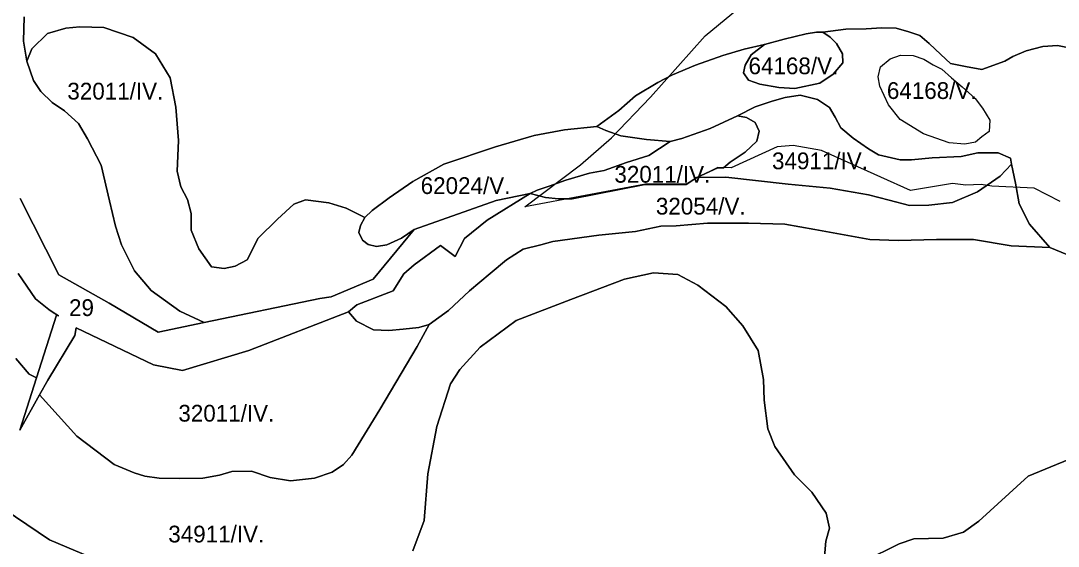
# Model space of a CAD drawing. Extents: x -521621 to -516761, y -1190184 to -1184927.
# Drawn here: x -518666 to -517738, y -1186473 to -1186003 of the extents above; entities that cross this region are included whole.
import ezdxf

# ---------------------------------------------------------------- set-up
doc = ezdxf.new("R2010")
doc.units = 0
doc.layers.add('BPEJ_s', color=7, linetype='Continuous')
doc.layers.add('odvodneni_s', color=7, linetype='Continuous')

msp = doc.modelspace()

# ---------------------------------------------------------------- linework, layer by layer
at = {"layer": 'BPEJ_s'}
for points in [[(-518663.33, -1185999.19), (-518663.92, -1186020.8), (-518660.96, -1186038.86), (-518655.06, -1186055.93), (-518648.33, -1186066.04), (-518638.23, -1186075.72), (-518627.28, -1186083.3), (-518614.66, -1186094.67), (-518606.66, -1186108.15), (-518594.46, -1186131.73), (-518586.88, -1186163.74), (-518581.41, -1186186.48), (-518576.05, -1186203.16), (-518564.51, -1186226.26), (-518549.71, -1186244.02), (-518523.97, -1186262.37), (-518502.28, -1186272.68), (-518543.48, -1186281.2), (-518587.23, -1186255.36), (-518632.34, -1186230.07), (-518666.87, -1186161.64)], [(-517723.47, -1186027.82), (-517738.12, -1186024.66), (-517751.18, -1186025.57), (-517766.28, -1186029.4), (-517778.07, -1186034.66), (-517785.38, -1186038.88), (-517805.91, -1186046.19), (-517820.53, -1186043.66), (-517834.02, -1186040.84), (-517842.74, -1186032.69), (-517853.14, -1186022.84), (-517861.3, -1186015.81), (-517871.42, -1186012.43), (-517882.67, -1186009.34), (-517895.32, -1186009.05), (-517909.38, -1186009.9), (-517927.65, -1186010.18), (-517948.18, -1186012.71), (-517954.08, -1186012.71), (-517963.08, -1186014.4), (-517982.76, -1186019.18), (-518000.47, -1186023.97), (-518018.75, -1186027.9), (-518037.87, -1186033.81), (-518062.33, -1186042.25), (-518082.86, -1186050.97), (-518096.07, -1186057.73), (-518116.03, -1186069.82), (-518130.93, -1186083.05), (-518150.62, -1186097.11), (-518179.58, -1186100.21), (-518206.57, -1186105.27), (-518241.43, -1186115.4), (-518287.54, -1186130.87), (-518315.38, -1186146.34), (-518336.47, -1186160.97), (-518351.65, -1186172.51), (-518358.4, -1186178.7), (-518374.99, -1186170.26), (-518390.45, -1186165.48), (-518411.54, -1186162.94), (-518421.91, -1186166.68), (-518436.64, -1186180.16), (-518453.89, -1186197), (-518463.57, -1186216.37), (-518474.51, -1186222.27), (-518484.19, -1186224.37), (-518495.56, -1186222.69), (-518506.92, -1186206.69), (-518513.65, -1186189.84), (-518513.65, -1186175.1), (-518517.02, -1186162.47), (-518522.91, -1186151.1), (-518526.28, -1186137.21), (-518525.02, -1186109.83), (-518527.54, -1186079.93), (-518532.59, -1186053.82), (-518545.64, -1186032.35), (-518565.84, -1186017.61), (-518591.93, -1186008.77), (-518613.33, -1186008.07), (-518626.05, -1186009.25), (-518642.32, -1186013.99), (-518656.52, -1186027.61), (-518660.96, -1186038.86), (-518663.92, -1186020.8), (-518663.33, -1185999.19)], [(-517724.74, -1186213.79), (-517745.18, -1186205.51), (-517763.2, -1186184.56), (-517772.44, -1186166.54), (-517775.85, -1186148.03), (-517779.26, -1186130.98), (-517780.23, -1186125.62), (-517791.43, -1186120.75), (-517809.44, -1186120.75), (-517824.54, -1186124.16), (-517850.34, -1186125.14), (-517868.84, -1186127.08), (-517879.06, -1186127.08), (-517898.53, -1186122.7), (-517907.3, -1186117.34), (-517921.18, -1186107.8), (-517932.15, -1186098.52), (-517937.21, -1186088.95), (-517942.27, -1186080.23), (-517952.96, -1186073.2), (-517968.42, -1186069.26), (-517981.92, -1186071.23), (-517993.73, -1186074.6), (-518008.91, -1186079.67), (-518024.65, -1186087.83), (-518049.12, -1186099.08), (-518074.42, -1186108.08), (-518084.82, -1186110.62), (-518106.19, -1186108.93), (-518129.25, -1186105.55), (-518142.46, -1186100.77), (-518150.62, -1186097.11), (-518130.93, -1186083.05), (-518116.03, -1186069.82), (-518096.07, -1186057.73), (-518082.86, -1186050.97), (-518062.33, -1186042.25), (-518037.87, -1186033.81), (-518018.75, -1186027.9), (-518000.47, -1186023.97), (-518012.56, -1186033.25), (-518017.91, -1186042.25), (-518019.31, -1186049.29), (-518014.81, -1186055.76), (-518004.69, -1186059.41), (-517987.54, -1186062.23), (-517973.48, -1186063.35), (-517950.99, -1186058.57), (-517938.9, -1186050.41), (-517930.46, -1186040.28), (-517930.75, -1186032.12), (-517936.09, -1186022.84), (-517941.71, -1186017.21), (-517948.18, -1186012.71), (-517927.65, -1186010.18), (-517909.38, -1186009.9), (-517895.32, -1186009.05), (-517882.67, -1186009.34), (-517871.42, -1186012.43), (-517861.3, -1186015.81), (-517853.14, -1186022.84), (-517842.74, -1186032.69), (-517834.02, -1186040.84), (-517820.53, -1186043.66), (-517805.91, -1186046.19), (-517785.38, -1186038.88), (-517778.07, -1186034.66), (-517766.28, -1186029.4), (-517751.18, -1186025.57), (-517738.12, -1186024.66), (-517723.47, -1186027.82)], [(-518666.87, -1186161.64), (-518632.34, -1186230.07), (-518587.23, -1186255.36), (-518543.48, -1186281.2), (-518502.28, -1186272.68), (-518398.58, -1186251.24), (-518388.54, -1186249.6), (-518350.76, -1186233.82), (-518314.06, -1186189.3), (-518240.84, -1186163.54), (-518210.39, -1186157.15), (-518248.83, -1186181.17), (-518269.07, -1186197.45), (-518277.37, -1186213.57), (-518290.59, -1186203.73), (-518314, -1186220.9), (-518323.49, -1186229.17), (-518332.99, -1186244.14), (-518365.52, -1186256.64), (-518373.06, -1186263.06), (-518462.29, -1186297.62), (-518521.64, -1186315.37), (-518547.55, -1186310.37), (-518616.73, -1186277.29), (-518618.04, -1186284.1), (-518642.2, -1186324.24), (-518649.43, -1186337.23), (-518667.13, -1186369), (-518652.28, -1186322.17), (-518634.49, -1186266.09), (-518632.69, -1186266.61), (-518638.34, -1186263), (-518641.17, -1186260.95), (-518653.25, -1186251.43), (-518668.53, -1186228.68)], [(-518670.73, -1186304.88), (-518658.79, -1186318.79), (-518652.28, -1186322.17), (-518667.13, -1186369), (-518649.43, -1186337.23), (-518616.27, -1186374.14), (-518582.58, -1186399.67), (-518564.92, -1186407.2), (-518555.21, -1186409.96), (-518542.56, -1186411.92), (-518524.29, -1186412.21), (-518503.2, -1186411.92), (-518488.3, -1186409.11), (-518477.33, -1186405.74), (-518459.9, -1186405.45), (-518443.03, -1186411.36), (-518424.75, -1186414.18), (-518403.38, -1186411.93), (-518387.64, -1186406.58), (-518377.52, -1186399.55), (-518369.85, -1186391.33), (-518344.96, -1186350.52), (-518311.57, -1186294), (-518300.57, -1186274.34), (-518283.33, -1186261.69), (-518264.49, -1186244.25), (-518246.21, -1186228.78), (-518231.59, -1186216.4), (-518216.69, -1186207.11), (-518200.66, -1186203.17), (-518189.98, -1186200.08), (-518148.78, -1186194.48), (-518115.95, -1186191.11), (-518093.26, -1186186.51), (-518079.63, -1186186.03), (-518051.4, -1186183.59), (-518014.88, -1186183.59), (-517982.27, -1186184.56), (-517955.49, -1186189.44), (-517906.32, -1186198.2), (-517880.52, -1186199.18), (-517846.44, -1186198.2), (-517813.34, -1186198.2), (-517779.75, -1186204.05), (-517745.18, -1186205.51), (-517724.74, -1186213.79)], [(-518668.53, -1186228.68), (-518653.25, -1186251.43), (-518641.17, -1186260.95), (-518638.34, -1186263), (-518632.69, -1186266.61), (-518634.49, -1186266.09), (-518652.28, -1186322.17), (-518658.79, -1186318.79), (-518670.73, -1186304.88)], [(-518315.38, -1186476.97), (-518305.23, -1186449.66), (-518302.05, -1186408.06), (-518293.8, -1186365.51), (-518281.74, -1186327.4), (-518273.17, -1186314.7), (-518255.08, -1186294.69), (-518222.71, -1186270.88), (-518173.84, -1186252.14), (-518125.91, -1186233.72), (-518099.89, -1186228), (-518077.99, -1186229.59), (-518060.22, -1186239.12), (-518035.15, -1186258.17), (-518019.91, -1186275.64), (-518006.26, -1186297.55), (-518001.5, -1186323.59), (-518000.87, -1186342.01), (-517997.38, -1186367.73), (-517991.35, -1186383.61), (-517973.58, -1186408.7), (-517958.02, -1186424.26), (-517945.33, -1186442.99), (-517942.16, -1186456.65), (-517945.65, -1186468.08), (-517946.92, -1186482.05)], [(-517946.92, -1186482.05), (-517945.65, -1186468.08), (-517942.16, -1186456.65), (-517945.33, -1186442.99), (-517958.02, -1186424.26), (-517973.58, -1186408.7), (-517991.35, -1186383.61), (-517997.38, -1186367.73), (-518000.87, -1186342.01), (-518001.5, -1186323.59), (-518006.26, -1186297.55), (-518019.91, -1186275.64), (-518035.15, -1186258.17), (-518060.22, -1186239.12), (-518077.99, -1186229.59), (-518099.89, -1186228), (-518125.91, -1186233.72), (-518173.84, -1186252.14), (-518222.71, -1186270.88), (-518255.08, -1186294.69), (-518273.17, -1186314.7), (-518281.74, -1186327.4), (-518293.8, -1186365.51), (-518302.05, -1186408.06), (-518305.23, -1186449.66), (-518315.38, -1186476.97)], [(-517911.12, -1186485.97), (-517879.79, -1186470.53), (-517866.88, -1186466.11), (-517840.6, -1186465.48), (-517822.33, -1186460.12), (-517808.67, -1186450.41), (-517764.3, -1186409.9), (-517707.01, -1186386.47)], [(-517707.01, -1186386.47), (-517764.3, -1186409.9), (-517808.67, -1186450.41), (-517822.33, -1186460.12), (-517840.6, -1186465.48), (-517866.88, -1186466.11), (-517879.79, -1186470.53), (-517911.12, -1186485.97)], [(-518681.31, -1186439.5), (-518640.68, -1186467.13), (-518559.44, -1186501.43)], [(-518559.44, -1186501.43), (-518640.68, -1186467.13), (-518681.31, -1186439.5)]]:
    msp.add_lwpolyline(points, dxfattribs=at)
for points in [[(-518660.96, -1186038.86), (-518656.52, -1186027.61), (-518642.32, -1186013.99), (-518626.05, -1186009.25), (-518613.33, -1186008.07), (-518591.93, -1186008.77), (-518565.84, -1186017.61), (-518545.64, -1186032.35), (-518532.59, -1186053.82), (-518527.54, -1186079.93), (-518525.02, -1186109.83), (-518526.28, -1186137.21), (-518522.91, -1186151.1), (-518517.02, -1186162.47), (-518513.65, -1186175.1), (-518513.65, -1186189.84), (-518506.92, -1186206.69), (-518495.56, -1186222.69), (-518484.19, -1186224.37), (-518474.51, -1186222.27), (-518463.57, -1186216.37), (-518453.89, -1186197), (-518436.64, -1186180.16), (-518421.91, -1186166.68), (-518411.54, -1186162.94), (-518390.45, -1186165.48), (-518374.99, -1186170.26), (-518358.4, -1186178.7), (-518362.33, -1186185.73), (-518363.74, -1186192.2), (-518360.37, -1186198.95), (-518355.3, -1186202.89), (-518347.99, -1186204.58), (-518338.72, -1186203.17), (-518325.5, -1186197.27), (-518314.06, -1186189.3), (-518350.76, -1186233.82), (-518388.54, -1186249.6), (-518398.58, -1186251.24), (-518502.28, -1186272.68), (-518523.97, -1186262.37), (-518549.71, -1186244.02), (-518564.51, -1186226.26), (-518576.05, -1186203.16), (-518581.41, -1186186.48), (-518586.88, -1186163.74), (-518594.46, -1186131.73), (-518606.66, -1186108.15), (-518614.66, -1186094.67), (-518627.28, -1186083.3), (-518638.23, -1186075.72), (-518648.33, -1186066.04), (-518655.06, -1186055.93)], [(-518000.47, -1186023.97), (-517982.76, -1186019.18), (-517963.08, -1186014.4), (-517954.08, -1186012.71), (-517948.18, -1186012.71), (-517941.71, -1186017.21), (-517936.09, -1186022.84), (-517930.75, -1186032.12), (-517930.46, -1186040.28), (-517938.9, -1186050.41), (-517950.99, -1186058.57), (-517973.48, -1186063.35), (-517987.54, -1186062.23), (-518004.69, -1186059.41), (-518014.81, -1186055.76), (-518019.31, -1186049.29), (-518017.91, -1186042.25), (-518012.56, -1186033.25)], [(-517878.73, -1186033.53), (-517867.48, -1186033.81), (-517857.92, -1186036.91), (-517849.49, -1186041.97), (-517841.62, -1186045.91), (-517833.18, -1186053.79), (-517823.62, -1186061.66), (-517811.81, -1186072.07), (-517805.35, -1186080.8), (-517798.88, -1186091.49), (-517799.44, -1186101.61), (-517805.91, -1186106.4), (-517811.53, -1186111.18), (-517821.09, -1186113.15), (-517835.15, -1186111.74), (-517858.2, -1186103.86), (-517879.01, -1186090.92), (-517889.41, -1186077.7), (-517897.29, -1186061.1), (-517898.69, -1186052.94), (-517896.72, -1186043.94), (-517888.01, -1186036.62)], [(-517878.73, -1186033.53), (-517867.48, -1186033.81), (-517857.92, -1186036.91), (-517849.49, -1186041.97), (-517841.62, -1186045.91), (-517833.18, -1186053.79), (-517823.62, -1186061.66), (-517811.81, -1186072.07), (-517805.35, -1186080.8), (-517798.88, -1186091.49), (-517799.44, -1186101.61), (-517805.91, -1186106.4), (-517811.53, -1186111.18), (-517821.09, -1186113.15), (-517835.15, -1186111.74), (-517858.2, -1186103.86), (-517879.01, -1186090.92), (-517889.41, -1186077.7), (-517897.29, -1186061.1), (-517898.69, -1186052.94), (-517896.72, -1186043.94), (-517888.01, -1186036.62)], [(-518061, -1186142.84), (-518042.26, -1186134.13), (-518037.17, -1186134.19), (-518031.12, -1186129.18), (-518017.91, -1186120.18), (-518007.5, -1186110.33), (-518005.25, -1186101.33), (-518008.91, -1186093.74), (-518016.5, -1186089.24), (-518024.65, -1186087.83), (-518008.91, -1186079.67), (-517993.73, -1186074.6), (-517981.92, -1186071.23), (-517968.42, -1186069.26), (-517952.96, -1186073.2), (-517942.27, -1186080.23), (-517937.21, -1186088.95), (-517932.15, -1186098.52), (-517921.18, -1186107.8), (-517907.3, -1186117.34), (-517898.53, -1186122.7), (-517879.06, -1186127.08), (-517868.84, -1186127.08), (-517850.34, -1186125.14), (-517824.54, -1186124.16), (-517809.44, -1186120.75), (-517791.43, -1186120.75), (-517780.23, -1186125.62), (-517779.26, -1186130.98), (-517789.48, -1186141.7), (-517809.93, -1186155.82), (-517832.32, -1186165.08), (-517853.26, -1186167.52), (-517870.78, -1186168), (-517888.8, -1186163.13), (-517907.3, -1186158.26), (-517921.19, -1186155.91), (-517941.71, -1186152.26), (-517979.39, -1186148.88), (-518035.06, -1186142.69)], [(-518210.39, -1186157.15), (-518204.04, -1186154.22), (-518193.35, -1186150.56), (-518178.45, -1186145.22), (-518157.08, -1186139.03), (-518144.15, -1186136.5), (-518123.91, -1186129.47), (-518103.94, -1186123.28), (-518084.82, -1186110.62), (-518074.42, -1186108.08), (-518049.12, -1186099.08), (-518024.65, -1186087.83), (-518016.5, -1186089.24), (-518008.91, -1186093.74), (-518005.25, -1186101.33), (-518007.5, -1186110.33), (-518017.91, -1186120.18), (-518031.12, -1186129.18), (-518037.17, -1186134.19), (-518042.26, -1186134.13), (-518061, -1186142.84), (-518070.68, -1186148.97), (-518107.68, -1186149.19), (-518172.62, -1186161.96), (-518184.92, -1186161.82), (-518196.45, -1186160.69)], [(-518358.4, -1186178.7), (-518351.65, -1186172.51), (-518336.47, -1186160.97), (-518315.38, -1186146.34), (-518287.54, -1186130.87), (-518241.43, -1186115.4), (-518206.57, -1186105.27), (-518179.58, -1186100.21), (-518150.62, -1186097.11), (-518142.46, -1186100.77), (-518129.25, -1186105.55), (-518106.19, -1186108.93), (-518084.82, -1186110.62), (-518103.94, -1186123.28), (-518123.91, -1186129.47), (-518144.15, -1186136.5), (-518157.08, -1186139.03), (-518178.45, -1186145.22), (-518193.35, -1186150.56), (-518204.04, -1186154.22), (-518210.39, -1186157.15), (-518240.84, -1186163.54), (-518314.06, -1186189.3), (-518325.5, -1186197.27), (-518338.72, -1186203.17), (-518347.99, -1186204.58), (-518355.3, -1186202.89), (-518360.37, -1186198.95), (-518363.74, -1186192.2), (-518362.33, -1186185.73)], [(-518373.06, -1186263.06), (-518365.52, -1186256.64), (-518332.99, -1186244.14), (-518323.49, -1186229.17), (-518314, -1186220.9), (-518290.59, -1186203.73), (-518277.37, -1186213.57), (-518269.07, -1186197.45), (-518248.83, -1186181.17), (-518210.39, -1186157.15), (-518196.45, -1186160.69), (-518184.92, -1186161.82), (-518172.62, -1186161.96), (-518107.68, -1186149.19), (-518070.68, -1186148.97), (-518061, -1186142.84), (-518035.06, -1186142.69), (-517979.39, -1186148.88), (-517941.71, -1186152.26), (-517921.19, -1186155.91), (-517907.3, -1186158.26), (-517888.8, -1186163.13), (-517870.78, -1186168), (-517853.26, -1186167.52), (-517832.32, -1186165.08), (-517809.93, -1186155.82), (-517789.48, -1186141.7), (-517779.26, -1186130.98), (-517775.85, -1186148.03), (-517772.44, -1186166.54), (-517763.2, -1186184.56), (-517745.18, -1186205.51), (-517779.75, -1186204.05), (-517813.34, -1186198.2), (-517846.44, -1186198.2), (-517880.52, -1186199.18), (-517906.32, -1186198.2), (-517955.49, -1186189.44), (-517982.27, -1186184.56), (-518014.88, -1186183.59), (-518051.4, -1186183.59), (-518079.63, -1186186.03), (-518093.26, -1186186.51), (-518115.95, -1186191.11), (-518148.78, -1186194.48), (-518189.98, -1186200.08), (-518200.66, -1186203.17), (-518216.69, -1186207.11), (-518231.59, -1186216.4), (-518246.21, -1186228.78), (-518264.49, -1186244.25), (-518283.33, -1186261.69), (-518300.57, -1186274.34), (-518310.04, -1186277.17), (-518324.1, -1186278.57), (-518336.75, -1186279.7), (-518350.52, -1186279.14), (-518365.71, -1186271.26)], [(-518649.43, -1186337.23), (-518642.2, -1186324.24), (-518618.04, -1186284.1), (-518616.73, -1186277.29), (-518547.55, -1186310.37), (-518521.64, -1186315.37), (-518462.29, -1186297.62), (-518373.06, -1186263.06), (-518365.71, -1186271.26), (-518350.52, -1186279.14), (-518336.75, -1186279.7), (-518324.1, -1186278.57), (-518310.04, -1186277.17), (-518300.57, -1186274.34), (-518311.57, -1186294), (-518344.96, -1186350.52), (-518369.85, -1186391.33), (-518377.52, -1186399.55), (-518387.64, -1186406.58), (-518403.38, -1186411.93), (-518424.75, -1186414.18), (-518443.03, -1186411.36), (-518459.9, -1186405.45), (-518477.33, -1186405.74), (-518488.3, -1186409.11), (-518503.2, -1186411.92), (-518524.29, -1186412.21), (-518542.56, -1186411.92), (-518555.21, -1186409.96), (-518564.92, -1186407.2), (-518582.58, -1186399.67), (-518616.27, -1186374.14)]]:
    msp.add_lwpolyline(points, close=True, dxfattribs=at)
at = {"layer": 'odvodneni_s'}
msp.add_lwpolyline([(-517735.74, -1186164.22), (-517759.02, -1186152.37), (-517797.05, -1186150.63), (-517806.6, -1186149.18), (-517820.34, -1186149.76), (-517832.05, -1186148.17), (-517869.65, -1186154.54), (-517949.33, -1186118.82), (-517974.78, -1186114.19), (-517989.24, -1186115.35), (-518030.31, -1186134.29), (-518042.17, -1186134), (-518059.38, -1186142.39), (-518070.37, -1186148.46), (-518107.1, -1186148.75), (-518214.98, -1186169), (-518165.09, -1186131.54), (-518137.47, -1186107.25), (-518102.62, -1186070.95), (-518053.59, -1186016), (-517971.74, -1185948.32)], dxfattribs=at)

# ---------------------------------------------------------------- texts
at = {"layer": 'BPEJ_s'}
for s, p in [('64168/V.', (-518014.78, -1186050.46)), ('32011/IV.', (-518624.63, -1186073.1)), ('64168/V.', (-517890.92, -1186072.6)), ('34911/IV.', (-517993.76, -1186135.47)), ('32011/IV.', (-518134.89, -1186147.48)), ('62024/V.', (-518308.3, -1186157.62)), ('32054/V.', (-518097.73, -1186176.01)), ('29', (-518623.12, -1186266.78)), ('32011/IV.', (-518525.25, -1186361.24)), ('34911/IV.', (-518534.26, -1186469.34))]:
    msp.add_text(s, height=15, dxfattribs=at).set_placement(p)

doc.saveas('drawing.dxf')
